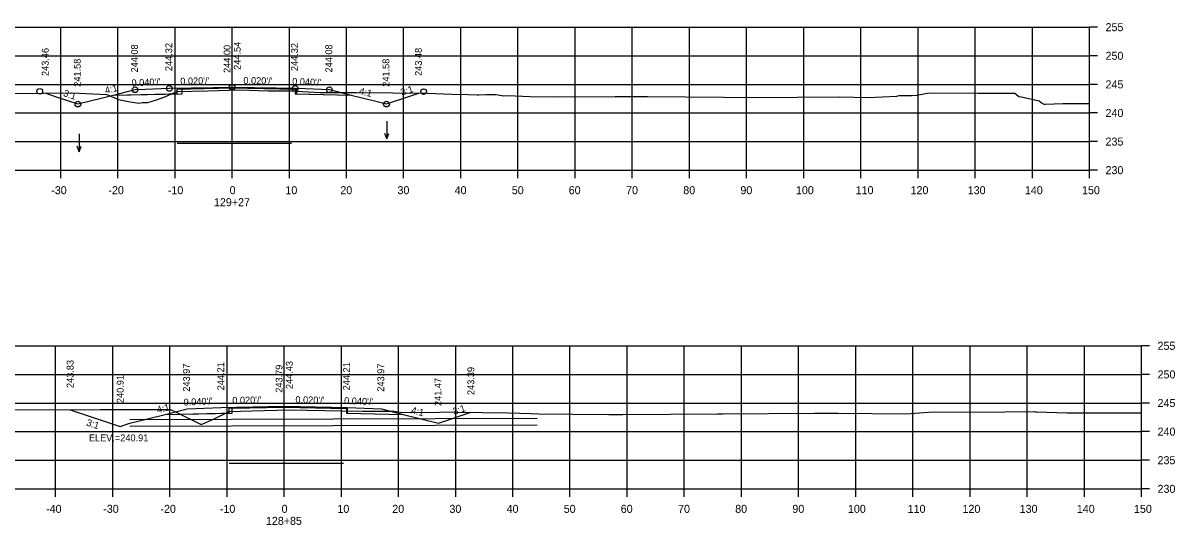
# Model space of a CAD drawing. Extents: x 1369627 to 1374022, y 380035 to 398173.
# Drawn here: x 1369747 to 1369948.5, y 382439.3 to 382527 of the extents above; entities that cross this region are included whole.
import ezdxf

# ---------------------------------------------------------------- set-up
doc = ezdxf.new("R2010")
doc.units = 0
for name, color, linetype in [('Default', 7, 'Continuous'), ('R_Alt Surface', 7, 'Continuous'), ('R_Axis', 7, 'Continuous'), ('R_Axis Annot', 7, 'Continuous'), ('R_Border Notes', 7, 'Continuous'), ('R_Exist Surface', 7, 'Continuous'), ('R_Fin Surface', 7, 'Continuous'), ('R_Grid', 7, 'Continuous'), ('R_No Plot', 7, 'Continuous'), ('R_Water', 7, 'Continuous'), ('R_Water Annot', 7, 'Continuous'), ('R_Xsect Elev', 7, 'Continuous'), ('R_Xsect Slope', 7, 'Continuous')]:
    doc.layers.add(name, color=color, linetype=linetype)

msp = doc.modelspace()

# ---------------------------------------------------------------- linework, layer by layer
at = {"layer": 'Default'}
for points in [[(1369774.82, 382506.31), (1369786.82, 382506.31), (1369794.82, 382506.31)], [(1369773.93, 382506.02), (1369781.93, 382506.02), (1369793.93, 382506.02)], [(1369783.05, 382450.07), (1369803.05, 382450.07)]]:
    msp.add_lwpolyline(points, dxfattribs=at)
at = {"layer": 'R_Alt Surface'}
for points in [[(1369762.73, 382514.41), (1369772.55, 382514.6), (1369773.93, 382514.63), (1369773.93, 382515.46), (1369783.55, 382515.66), (1369794.55, 382515.44), (1369794.55, 382514.61), (1369794.55, 382514.61), (1369804.36, 382514.41)], [(1369762.73, 382514.41), (1369774.82, 382514.65), (1369774.82, 382515.48), (1369783.55, 382515.66), (1369794.82, 382515.43), (1369794.82, 382514.6), (1369804.38, 382514.41)], [(1369771.82, 382458.59), (1369781.65, 382458.79), (1369783.05, 382458.82), (1369783.05, 382459.65), (1369792.65, 382459.84), (1369803.65, 382459.62), (1369803.65, 382458.79), (1369803.65, 382458.79), (1369813.46, 382458.59)], [(1369771.82, 382458.59), (1369783.53, 382458.82), (1369783.53, 382459.66), (1369792.65, 382459.84), (1369803.53, 382459.62), (1369803.53, 382458.79), (1369813.47, 382458.59)]]:
    msp.add_lwpolyline(points, dxfattribs=at)
at = {"layer": 'R_Axis'}
for p, q in [((1369933.55, 382501.28), (1369933.55, 382526.28)), ((1369934.95, 382526.28), (1369933.55, 382526.28)), ((1369934.95, 382521.28), (1369933.55, 382521.28)), ((1369934.95, 382516.28), (1369933.55, 382516.28)), ((1369934.95, 382511.28), (1369933.55, 382511.28)), ((1369934.95, 382506.28), (1369933.55, 382506.28)), ((1369633.55, 382501.28), (1369933.55, 382501.28)), ((1369753.55, 382499.88), (1369753.55, 382501.28)), ((1369763.55, 382499.88), (1369763.55, 382501.28)), ((1369773.55, 382499.88), (1369773.55, 382501.28)), ((1369783.55, 382499.88), (1369783.55, 382501.28)), ((1369793.55, 382499.88), (1369793.55, 382501.28)), ((1369803.55, 382499.88), (1369803.55, 382501.28)), ((1369813.55, 382499.88), (1369813.55, 382501.28)), ((1369823.55, 382499.88), (1369823.55, 382501.28)), ((1369833.55, 382499.88), (1369833.55, 382501.28)), ((1369843.55, 382499.88), (1369843.55, 382501.28)), ((1369853.55, 382499.88), (1369853.55, 382501.28)), ((1369863.55, 382499.88), (1369863.55, 382501.28)), ((1369873.55, 382499.88), (1369873.55, 382501.28)), ((1369883.55, 382499.88), (1369883.55, 382501.28)), ((1369893.55, 382499.88), (1369893.55, 382501.28)), ((1369903.55, 382499.88), (1369903.55, 382501.28)), ((1369913.55, 382499.88), (1369913.55, 382501.28)), ((1369923.55, 382499.88), (1369923.55, 382501.28)), ((1369933.55, 382499.88), (1369933.55, 382501.28)), ((1369934.95, 382501.28), (1369933.55, 382501.28)), ((1369942.65, 382445.57), (1369942.65, 382470.57)), ((1369944.05, 382470.57), (1369942.65, 382470.57)), ((1369944.05, 382465.57), (1369942.65, 382465.57)), ((1369944.05, 382460.57), (1369942.65, 382460.57)), ((1369944.05, 382455.57), (1369942.65, 382455.57)), ((1369944.05, 382450.57), (1369942.65, 382450.57)), ((1369642.65, 382445.57), (1369942.65, 382445.57)), ((1369752.65, 382444.17), (1369752.65, 382445.57)), ((1369762.65, 382444.17), (1369762.65, 382445.57)), ((1369772.65, 382444.17), (1369772.65, 382445.57)), ((1369782.65, 382444.17), (1369782.65, 382445.57)), ((1369792.65, 382444.17), (1369792.65, 382445.57)), ((1369802.65, 382444.17), (1369802.65, 382445.57)), ((1369812.65, 382444.17), (1369812.65, 382445.57)), ((1369822.65, 382444.17), (1369822.65, 382445.57)), ((1369832.65, 382444.17), (1369832.65, 382445.57)), ((1369842.65, 382444.17), (1369842.65, 382445.57)), ((1369852.65, 382444.17), (1369852.65, 382445.57)), ((1369862.65, 382444.17), (1369862.65, 382445.57)), ((1369872.65, 382444.17), (1369872.65, 382445.57)), ((1369882.65, 382444.17), (1369882.65, 382445.57)), ((1369892.65, 382444.17), (1369892.65, 382445.57)), ((1369902.65, 382444.17), (1369902.65, 382445.57)), ((1369912.65, 382444.17), (1369912.65, 382445.57)), ((1369922.65, 382444.17), (1369922.65, 382445.57)), ((1369932.65, 382444.17), (1369932.65, 382445.57)), ((1369942.65, 382444.17), (1369942.65, 382445.57)), ((1369944.05, 382445.57), (1369942.65, 382445.57))]:
    msp.add_line(p, q, dxfattribs=at)
at = {"layer": 'R_Exist Surface'}
for points in [[(1369740.48, 382514.64), (1369755.5, 382514.78), (1369761.61, 382514.51), (1369763.67, 382513.64), (1369765.4, 382513.3), (1369766.03, 382513.19), (1369767.29, 382512.99), (1369767.81, 382513.09), (1369768.78, 382513.11), (1369770.28, 382513.56), (1369771.75, 382514.13), (1369772.91, 382514.63), (1369773.93, 382515.02), (1369779.24, 382515.17), (1369784.82, 382515.31), (1369789.87, 382515.16), (1369793.88, 382515.13), (1369798.93, 382514.87), (1369799.27, 382514.86), (1369803.28, 382514.87), (1369804.04, 382514.86), (1369805.27, 382514.87), (1369811.68, 382514.83), (1369817.66, 382514.72), (1369821.96, 382514.56), (1369824.85, 382514.49), (1369826.41, 382514.45), (1369826.69, 382514.44), (1369827.91, 382514.51), (1369829.7, 382514.53), (1369831.08, 382514.29), (1369831.79, 382514.31), (1369835.6, 382514.16), (1369840.19, 382514.13), (1369850.58, 382514.16), (1369856.19, 382514.18), (1369869.5, 382514.03), (1369874.95, 382513.96), (1369889.86, 382514.09), (1369894.84, 382514.01), (1369899.84, 382514.2), (1369900.25, 382514.31), (1369900.88, 382514.34), (1369902.53, 382514.32), (1369903.35, 382514.37), (1369905.48, 382514.82), (1369914.03, 382514.76), (1369920.47, 382514.73), (1369921.17, 382514.18), (1369921.2, 382514.17), (1369921.24, 382514.17), (1369921.62, 382514.11), (1369924.72, 382513.38), (1369925.34, 382512.94), (1369925.6, 382512.82), (1369925.87, 382512.83), (1369928.89, 382512.96), (1369933.55, 382512.91)], [(1369724.15, 382459.31), (1369760.46, 382459.42), (1369772.75, 382459.42), (1369773.74, 382459), (1369778.11, 382456.81), (1369780.28, 382457.73), (1369783.05, 382459.07), (1369786.99, 382459.2), (1369793.53, 382459.39), (1369799.7, 382459.26), (1369802.71, 382459.18), (1369806.34, 382459.13), (1369807.54, 382459.12), (1369810.46, 382459.14), (1369811.88, 382459.13), (1369812.99, 382458.98), (1369814.76, 382458.94), (1369814.88, 382458.94), (1369819.84, 382458.99), (1369822.38, 382459.01), (1369822.45, 382459.01), (1369822.46, 382459.01), (1369822.54, 382459.01), (1369822.58, 382459.01), (1369822.68, 382459), (1369831.92, 382458.83), (1369835.86, 382458.73), (1369837.2, 382458.66), (1369843.14, 382458.62), (1369849.46, 382458.56), (1369851.89, 382458.55), (1369868.45, 382458.68), (1369869.39, 382458.69), (1369885.45, 382458.82), (1369886.86, 382458.82), (1369889.56, 382458.81), (1369901.4, 382458.69), (1369905.38, 382458.97), (1369918.75, 382459.05), (1369923.88, 382459.07), (1369924.22, 382458.97), (1369924.29, 382459.01), (1369929.59, 382458.85), (1369930.26, 382458.85), (1369930.42, 382458.86), (1369931.68, 382458.87), (1369935.13, 382458.88), (1369942.65, 382458.87)]]:
    msp.add_lwpolyline(points, dxfattribs=at)
at = {"layer": 'R_Fin Surface'}
for points in [[(1369750.94, 382514.74), (1369752.75, 382514.13), (1369756.55, 382512.86), (1369760.87, 382513.94), (1369762.73, 382514.41), (1369763.87, 382514.69), (1369766.55, 382515.36), (1369768.35, 382515.44), (1369772.55, 382515.6), (1369780.25, 382515.76), (1369783.55, 382515.82), (1369791.25, 382515.67), (1369794.55, 382515.6), (1369796.35, 382515.53), (1369800.55, 382515.36), (1369801.7, 382515.08), (1369804.36, 382514.41), (1369808.7, 382513.33), (1369810.55, 382512.86), (1369814.45, 382514.16), (1369816.23, 382514.76)], [(1369755.2, 382459.4), (1369763.96, 382456.48), (1369765.65, 382457.05), (1369771.82, 382458.59), (1369775.65, 382459.55), (1369781.65, 382459.79), (1369792.65, 382460.01), (1369803.65, 382459.79), (1369809.65, 382459.55), (1369813.46, 382458.59), (1369819.65, 382457.05), (1369825.37, 382458.95)]]:
    msp.add_lwpolyline(points, dxfattribs=at)
at = {"layer": 'R_Grid'}
for p, q in [((1369633.55, 382526.28), (1369933.55, 382526.28)), ((1369753.55, 382501.28), (1369753.55, 382526.28)), ((1369763.55, 382501.28), (1369763.55, 382526.28)), ((1369773.55, 382501.28), (1369773.55, 382526.28)), ((1369783.55, 382501.28), (1369783.55, 382526.28)), ((1369793.55, 382501.28), (1369793.55, 382526.28)), ((1369803.55, 382501.28), (1369803.55, 382526.28)), ((1369813.55, 382501.28), (1369813.55, 382526.28)), ((1369823.55, 382501.28), (1369823.55, 382526.28)), ((1369833.55, 382501.28), (1369833.55, 382526.28)), ((1369843.55, 382501.28), (1369843.55, 382526.28)), ((1369853.55, 382501.28), (1369853.55, 382526.28)), ((1369863.55, 382501.28), (1369863.55, 382526.28)), ((1369873.55, 382501.28), (1369873.55, 382526.28)), ((1369883.55, 382501.28), (1369883.55, 382526.28)), ((1369893.55, 382501.28), (1369893.55, 382526.28)), ((1369903.55, 382501.28), (1369903.55, 382526.28)), ((1369913.55, 382501.28), (1369913.55, 382526.28)), ((1369923.55, 382501.28), (1369923.55, 382526.28)), ((1369933.55, 382501.28), (1369933.55, 382526.28)), ((1369633.55, 382521.28), (1369933.55, 382521.28)), ((1369633.55, 382516.28), (1369933.55, 382516.28)), ((1369633.55, 382511.28), (1369933.55, 382511.28)), ((1369633.55, 382506.28), (1369933.55, 382506.28)), ((1369633.55, 382501.28), (1369933.55, 382501.28)), ((1369642.65, 382470.57), (1369942.65, 382470.57)), ((1369752.65, 382445.57), (1369752.65, 382470.57)), ((1369762.65, 382445.57), (1369762.65, 382470.57)), ((1369772.65, 382445.57), (1369772.65, 382470.57)), ((1369782.65, 382445.57), (1369782.65, 382470.57)), ((1369792.65, 382445.57), (1369792.65, 382470.57)), ((1369802.65, 382445.57), (1369802.65, 382470.57)), ((1369812.65, 382445.57), (1369812.65, 382470.57)), ((1369822.65, 382445.57), (1369822.65, 382470.57)), ((1369832.65, 382445.57), (1369832.65, 382470.57)), ((1369842.65, 382445.57), (1369842.65, 382470.57)), ((1369852.65, 382445.57), (1369852.65, 382470.57)), ((1369862.65, 382445.57), (1369862.65, 382470.57)), ((1369872.65, 382445.57), (1369872.65, 382470.57)), ((1369882.65, 382445.57), (1369882.65, 382470.57)), ((1369892.65, 382445.57), (1369892.65, 382470.57)), ((1369902.65, 382445.57), (1369902.65, 382470.57)), ((1369912.65, 382445.57), (1369912.65, 382470.57)), ((1369922.65, 382445.57), (1369922.65, 382470.57)), ((1369932.65, 382445.57), (1369932.65, 382470.57)), ((1369942.65, 382445.57), (1369942.65, 382470.57)), ((1369642.65, 382465.57), (1369942.65, 382465.57)), ((1369642.65, 382460.57), (1369942.65, 382460.57)), ((1369642.65, 382455.57), (1369942.65, 382455.57)), ((1369642.65, 382450.57), (1369942.65, 382450.57)), ((1369642.65, 382445.57), (1369942.65, 382445.57))]:
    msp.add_line(p, q, dxfattribs=at)
at = {"layer": 'R_No Plot'}
for centre in [(1369783.55, 382515.8), (1369749.89, 382515.06), (1369766.55, 382515.34), (1369772.55, 382515.58), (1369794.55, 382515.58), (1369800.55, 382515.34), (1369817.05, 382515.01), (1369756.55, 382512.84), (1369810.55, 382512.84)]:
    msp.add_circle(centre, 0.5, dxfattribs=at)
at = {"layer": 'R_Water'}
for p, q in [((1369836.91, 382457.84), (1369765.65, 382457.66)), ((1369836.91, 382456.67), (1369765.65, 382456.49))]:
    msp.add_line(p, q, dxfattribs=at)
at = {"layer": 'R_Water Annot'}
for p, q in [((1369810.59, 382509.87), (1369810.59, 382506.73)), ((1369756.78, 382507.65), (1369756.78, 382504.5)), ((1369810.59, 382506.73), (1369810.24, 382507.69)), ((1369810.59, 382506.73), (1369810.94, 382507.69)), ((1369756.78, 382504.5), (1369756.43, 382505.47)), ((1369756.78, 382504.5), (1369757.13, 382505.47))]:
    msp.add_line(p, q, dxfattribs=at)
at = {"layer": 'R_Xsect Elev'}
for p, q in [((1369783.55, 382515.28), (1369783.55, 382525.28)), ((1369792.65, 382459.37), (1369792.65, 382469.37))]:
    msp.add_line(p, q, dxfattribs=at)

# ---------------------------------------------------------------- texts
at = {"layer": 'R_Axis Annot'}
for s, p in [('255', (1369936.35, 382525.58)), ('250', (1369936.35, 382520.58)), ('245', (1369936.35, 382515.58)), ('240', (1369936.35, 382510.58)), ('235', (1369936.35, 382505.58)), ('230', (1369936.35, 382500.58)), ('-30', (1369751.89, 382497.08)), ('-20', (1369761.89, 382497.08)), ('-10', (1369772.29, 382497.08)), ('0', (1369783.1, 382497.08)), ('10', (1369792.86, 382497.08)), ('20', (1369802.47, 382497.08)), ('30', (1369812.47, 382497.08)), ('40', (1369822.47, 382497.08)), ('50', (1369832.47, 382497.08)), ('60', (1369842.43, 382497.08)), ('70', (1369852.47, 382497.08)), ('80', (1369862.47, 382497.08)), ('90', (1369872.47, 382497.08)), ('100', (1369882.18, 382497.08)), ('110', (1369892.63, 382497.08)), ('120', (1369902.24, 382497.08)), ('130', (1369912.24, 382497.08)), ('140', (1369922.24, 382497.08)), ('150', (1369932.24, 382497.08)), ('129+27', (1369780.36, 382494.98)), ('255', (1369945.45, 382469.87)), ('250', (1369945.45, 382464.87)), ('245', (1369945.45, 382459.87)), ('240', (1369945.45, 382454.87)), ('235', (1369945.45, 382449.87)), ('230', (1369945.45, 382444.87)), ('-40', (1369750.99, 382441.37)), ('-30', (1369760.99, 382441.37)), ('-20', (1369770.99, 382441.37)), ('-10', (1369781.39, 382441.37)), ('0', (1369792.19, 382441.37)), ('10', (1369801.96, 382441.37)), ('20', (1369811.56, 382441.37)), ('30', (1369821.56, 382441.37)), ('40', (1369831.56, 382441.37)), ('50', (1369841.56, 382441.37)), ('60', (1369851.53, 382441.37)), ('70', (1369861.56, 382441.37)), ('80', (1369871.56, 382441.37)), ('90', (1369881.56, 382441.37)), ('100', (1369891.28, 382441.37)), ('110', (1369901.73, 382441.37)), ('120', (1369911.33, 382441.37)), ('130', (1369921.33, 382441.37)), ('140', (1369931.33, 382441.37)), ('150', (1369941.33, 382441.37)), ('128+85', (1369789.45, 382439.27))]:
    msp.add_text(s, height=1.4, dxfattribs=at).set_placement(p)
at = {"layer": 'R_Border Notes'}
msp.add_text('ELEV.=240.91', height=1.2, dxfattribs=at).set_placement((1369758.48, 382453.88))
at = {"layer": 'R_Xsect Elev'}
for s, p in [('243.46', (1369751.44, 382517.74)), ('244.08', (1369767.05, 382518.36)), ('244.32', (1369773.05, 382518.6)), ('244.00', (1369783.25, 382518.28)), ('244.54', (1369785.04, 382518.82)), ('244.32', (1369795.05, 382518.6)), ('244.08', (1369801.05, 382518.36)), ('243.48', (1369816.73, 382517.76)), ('241.58', (1369757.05, 382515.86)), ('241.58', (1369811.05, 382515.86)), ('243.83', (1369755.8, 382463.19)), ('243.97', (1369776.15, 382462.55)), ('244.21', (1369782.15, 382462.79)), ('243.79', (1369792.35, 382462.37)), ('244.43', (1369794.14, 382463.01)), ('244.21', (1369804.15, 382462.79)), ('243.97', (1369810.15, 382462.55)), ('243.39', (1369825.91, 382461.97)), ('240.91', (1369764.56, 382460.56)), ('241.47', (1369820.15, 382460.05))]:
    msp.add_text(s, height=1.2, rotation=90, dxfattribs=at).set_placement(p)
at = {"layer": 'R_Xsect Slope'}
for s, rotation, p in [("0.040'/'", 2.2906, (1369765.97, 382515.94)), ("0.020'/'", 1.1458, (1369774.48, 382516.24)), ("0.020'/'", 358.8542, (1369785.5, 382516.38)), ("0.040'/'", 357.7094, (1369794.02, 382516.23)), ('3:1', 341.5651, (1369753.9, 382514.27)), ('4:1', 14.0362, (1369761.43, 382514.6)), ('4:1', 345.9638, (1369805.67, 382514.6)), ('3:1', 18.4349, (1369813.23, 382514.28)), ('4:1', 14.0362, (1369770.53, 382458.78)), ("0.040'/'", 2.2906, (1369775.07, 382460.12)), ("0.020'/'", 1.1458, (1369783.58, 382460.43)), ("0.020'/'", 358.8542, (1369794.6, 382460.57)), ("0.040'/'", 357.7094, (1369803.11, 382460.41)), ('3:1', 18.4349, (1369822.37, 382458.48)), ('4:1', 345.9638, (1369814.77, 382458.78)), ('3:1', 341.5651, (1369757.93, 382456.68))]:
    msp.add_text(s, height=1.2, rotation=rotation, dxfattribs=at).set_placement(p)

doc.saveas('drawing.dxf')
